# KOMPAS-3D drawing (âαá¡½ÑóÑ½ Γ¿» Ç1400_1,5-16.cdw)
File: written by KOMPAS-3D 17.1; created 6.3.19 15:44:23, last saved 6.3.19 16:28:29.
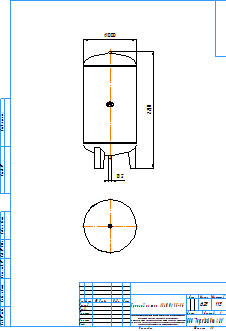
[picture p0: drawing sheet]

Sheet 1: A3, portrait

Title block, sheet 1: name: Гранлевел тип А1400/1,5-16; material: Сталь 10  ГОСТ 1050-88; mass: 625; sheets: 1; sheet format: A3; stored path: C:\Users\kka\KOMPAS_Work\!Trash\ГРАНЛЕВЕЛ тип А Расширительный бак\KOMPAS 2D\Гранлевел тип А1400_1,5-16.cdw

Views: Вид 1, Проекционный вид 2
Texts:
  kka
  adl
  Рама для чертежей
  Лит-Масса-Масштаб
  Материал-Предприятие
  Масштаб
  Изм.
  Лист
  № докум.
  Подп.
  Дата
  Лит.
  Разраб.
  Пров.
  Т.контр.
  Листов
  Внимание! Данный продукт является объектом авторского права ООО «Торговый Дом АДЛ».
  Запрещается изменение, копирование, распространение
  (в том числе путем копирования на другие сайты и ресурсы в Интернете)
  или любое иное использование информации и объектов без предварительного
  согласия правообладателя (ООО «Торговый Дом АДЛ»).
  Н.контр.
  Утв.
  ООО "Торговый дом АДЛ"
  Изменение
  Номер документа
  Подпись
  Обозначение документа
  Наименование изделия
  Масса изделия по ГОСТ 2.109-73
  Порядковый номер листа
  Общее количество листов в документе
  Характер работы, выполненной лицом, подписавшим документ
  Наименование или индекс предприятия, выпускающего документ
  Инв. № подл.
  Подп. и дата
  Взам. инв. №
  Инв. № дубл.
  Инвентарный номер подлинника по ГОСТ 2.501-68
  Подпись принявшего подлинник в отдел технической документации
  Инвентарный номер подлинника, взамен которого выпущен данный подлинник
  Инвентарный номер дубликата по ГОСТ 2.502-68
  Подпись принявшего дубликат в отдел технической документации
  Справ. №
  Перв. примен.
  Обозначение документа, взамен или на основании которого выпущен данный документ
  Обозначение документа, в котором впервые записан данный документ
  Подпись лица, копировавшего чертеж
  Обозначение формата листа
  !Рама для чертежа
Dimensions and other numbers on the sheet: 2210; 1000; 2; 1:15; 1; 625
